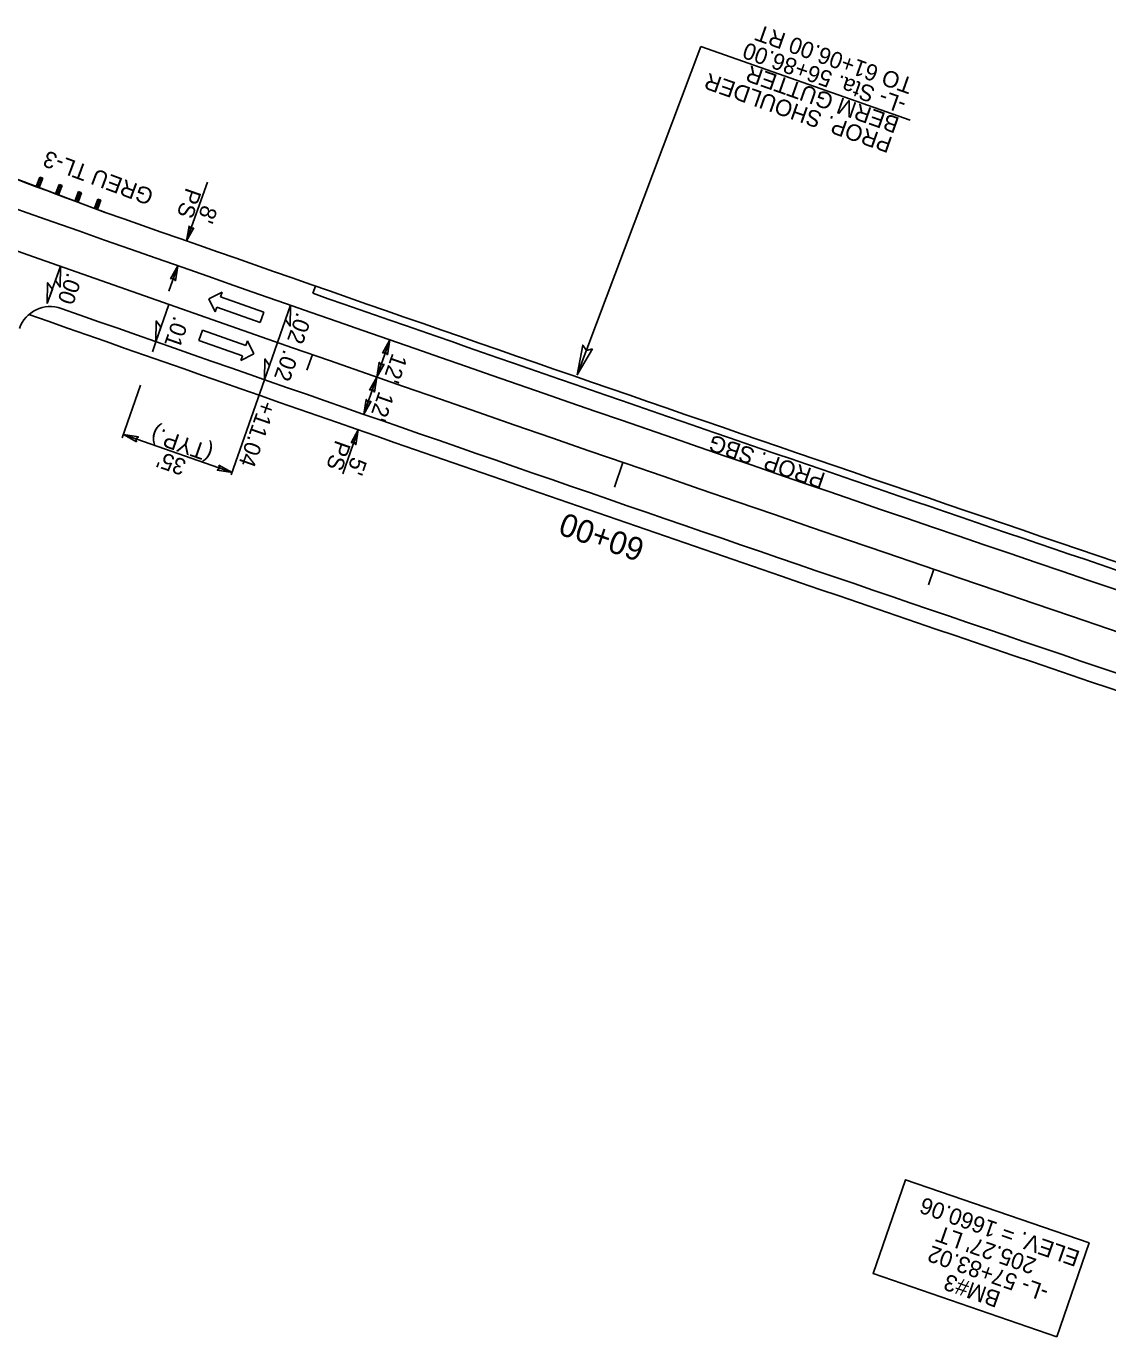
# Model space of a CAD drawing. Extents: x 472216 to 481979, y 489069 to 507339.
# Drawn here: x 479886.3 to 480215.3, y 493169 to 493567.7 of the extents above; entities that cross this region are included whole.
import ezdxf

# ---------------------------------------------------------------- set-up
doc = ezdxf.new("R2010")
doc.units = 0
for name, color, linetype in [('Exist Horizontal Alignment Point', 7, 'Continuous'), ('Prop Drainage Structure Drop Inlet Grate 2 Narrow Slots and Sag Grates 840 24 CELL', 7, 'Continuous'), ('Prop Drainage Structure Drop Inlet Grate 2 Wide Slots and Sag Grates 840 22 Label', 7, 'Continuous'), ('Prop Drainage Structure Outlet Berm Ditch 850 10 CELL', 7, 'Continuous'), ('Prop Drainage Structure Pipe CSP 15in', 7, 'Continuous'), ('Prop Drainage Structure Pipe Plug CELL', 7, 'Continuous'), ('Prop Drainage Structure Pipe RCP 24in Class III Label', 7, 'Continuous'), ('Prop Drainage Structure Pipe Side Drain 15in Label', 7, 'Continuous'), ('Prop Drainage Structure Tops and Inverts LABEL', 7, 'Continuous'), ('Prop Earthen Structure False Sump CELL', 7, 'Continuous'), ('Prop Erosion Embankment Toe Protection CELL', 7, 'Continuous'), ('Sheet Block Revision CELL', 7, 'Continuous'), ('Sheet North Arrow Point CELL', 7, 'Continuous'), ('Sheet PE Seal Cell', 7, 'Continuous'), ('Sheet Profile Grid Major CELL', 7, 'Continuous'), ('Sheet Profile Grid Minor CELL', 7, 'Continuous')]:
    doc.layers.add(name, color=color, linetype=linetype)

msp = doc.modelspace()

# ---------------------------------------------------------------- linework, layer by layer
at = {"layer": 'Exist Horizontal Alignment Point'}
msp.add_lwpolyline([(480199.77, 493168.96), (480143.94, 493188.2), (480153.78, 493216.75), (480209.61, 493197.51)], close=True, dxfattribs=at)
at = {"layer": 'Prop Drainage Structure Drop Inlet Grate 2 Narrow Slots and Sag Grates 840 24 CELL'}
for points in [[(479896.73, 493494.66), (479896.64, 493488.33), (479895.2, 493490.29)], [(479892.74, 493483.34), (479892.84, 493489.66), (479894.28, 493487.7)], [(479966.74, 493482.81), (479966.65, 493476.48), (479965.22, 493478.44)], [(479925.78, 493471.72), (479925.88, 493478.05), (479927.31, 493476.09)], [(479958.82, 493460.15), (479958.92, 493466.47), (479960.35, 493464.51)]]:
    msp.add_lwpolyline(points, close=True, dxfattribs=at)
at = {"layer": 'Prop Drainage Structure Drop Inlet Grate 2 Wide Slots and Sag Grates 840 22 Label'}
for p, q in [((479892.74, 493483.34), (479896.73, 493494.66)), ((479925.78, 493471.72), (479929.75, 493483.05)), ((479958.82, 493460.15), (479966.74, 493482.81)), ((479925.78, 493471.72), (479924.69, 493468.62)), ((479921.13, 493458.48), (479915.52, 493442.51)), ((479958.82, 493460.15), (479948.7, 493431.2)), ((479948.94, 493431.89), (479915.9, 493443.47))]:
    msp.add_line(p, q, dxfattribs=at)
for points in [[(479919.89, 493441.25), (479915.9, 493443.47), (479920.43, 493442.73), (479919.63, 493442.16)], [(479944.95, 493434.11), (479948.94, 493431.89), (479944.41, 493432.63), (479945.22, 493433.2)]]:
    msp.add_lwpolyline(points, close=True, dxfattribs=at)
at = {"layer": 'Prop Drainage Structure Outlet Berm Ditch 850 10 CELL'}
for points in [[(479937.34, 493506.35), (479935.12, 493502.36), (479935.86, 493506.89), (479936.43, 493506.09)], [(479930.24, 493490.82), (479932.46, 493494.81), (479931.72, 493490.28), (479931.15, 493491.09)], [(479994.74, 493468.27), (479996.96, 493472.26), (479996.21, 493467.73), (479995.65, 493468.53)], [(480058.54, 493469.54), (480053.92, 493461.66), (480055.61, 493470.69), (480056.7, 493469.05)], [(479995.2, 493464.93), (479992.98, 493460.94), (479993.73, 493465.47), (479994.29, 493464.66)], [(479990.76, 493456.95), (479992.98, 493460.94), (479992.24, 493456.4), (479991.67, 493457.21)], [(479991.23, 493453.61), (479989, 493449.62), (479989.75, 493454.15), (479990.31, 493453.34)], [(479985.12, 493440.91), (479987.34, 493444.9), (479986.6, 493440.37), (479986.03, 493441.17)]]:
    msp.add_lwpolyline(points, close=True, dxfattribs=at)
at = {"layer": 'Prop Drainage Structure Pipe Plug CELL'}
for p, q in [((479910.36, 493511.06), (479866.6, 493527.5)), ((479889.35, 493518.95), (479890.42, 493521.8)), ((479889.88, 493520.38), (479891.35, 493521.44)), ((479890.29, 493518.6), (479891.35, 493521.44)), ((479891.35, 493521.44), (479890.42, 493521.8)), ((479890.42, 493521.8), (479890.82, 493520.02)), ((479890.82, 493520.02), (479889.35, 493518.95)), ((479890.29, 493518.6), (479889.35, 493518.95)), ((479890.82, 493520.02), (479889.88, 493520.38)), ((479890.29, 493518.6), (479889.88, 493520.38)), ((479895.25, 493516.74), (479896.32, 493519.59)), ((479896.72, 493517.81), (479895.25, 493516.74)), ((479895.78, 493518.16), (479897.26, 493519.24)), ((479896.72, 493517.81), (479895.78, 493518.16)), ((479896.18, 493516.39), (479895.78, 493518.16)), ((479896.18, 493516.39), (479897.26, 493519.24)), ((479897.26, 493519.24), (479896.32, 493519.59)), ((479896.32, 493519.59), (479896.72, 493517.81)), ((479901.15, 493514.52), (479902.22, 493517.38)), ((479901.68, 493515.95), (479903.16, 493517.03)), ((479902.08, 493514.17), (479903.16, 493517.03)), ((479903.16, 493517.03), (479902.22, 493517.38)), ((479902.22, 493517.38), (479902.62, 493515.6)), ((479902.62, 493515.6), (479901.15, 493514.52)), ((479902.62, 493515.6), (479901.68, 493515.95)), ((479902.08, 493514.17), (479901.68, 493515.95)), ((479907.05, 493512.31), (479908.1, 493515.11)), ((479907.05, 493512.31), (479907.57, 493513.71)), ((479908.51, 493513.36), (479907.05, 493512.31)), ((479907.57, 493513.71), (479909.04, 493514.76)), ((479908.51, 493513.36), (479907.57, 493513.71)), ((479907.57, 493513.71), (479907.98, 493511.95)), ((479907.98, 493511.95), (479909.04, 493514.76)), ((479909.04, 493514.76), (479908.1, 493515.11)), ((479908.1, 493515.11), (479908.51, 493513.36)), ((479907.98, 493511.95), (479907.05, 493512.31))]:
    msp.add_line(p, q, dxfattribs=at)
at = {"layer": 'Prop Drainage Structure Pipe RCP 24in Class III Label'}
msp.add_line((479973.53, 493486.44), (479974.3, 493488.64), dxfattribs=at)
for centre, radius, start, end in [((489862.97, 521790.84), 29988, 250.329766, 251.348324), ((479893.66, 493472.41), 10, 70.6057, 160.5714), ((489862.97, 521790.84), 30012, 250.605735, 251.348326)]:
    msp.add_arc(centre, radius, start, end, dxfattribs=at)
at = {"layer": 'Prop Drainage Structure Pipe Side Drain 15in Label'}
for p, q in [((479941.88, 493484.77), (479945.91, 493486.74)), ((479943.82, 493480.8), (479941.88, 493484.77)), ((479945.91, 493486.74), (479945.41, 493485.32)), ((479945.41, 493485.32), (479958.62, 493480.67)), ((479944.32, 493482.21), (479943.82, 493480.8)), ((479957.52, 493477.56), (479944.32, 493482.21)), ((479958.62, 493480.67), (479957.52, 493477.56)), ((479938.87, 493472.09), (479939.96, 493475.2)), ((479939.96, 493475.2), (479953.17, 493470.55)), ((479952.07, 493467.44), (479938.87, 493472.09)), ((479953.17, 493470.55), (479953.67, 493471.97)), ((479953.67, 493471.97), (479955.61, 493468)), ((479955.61, 493468), (479951.57, 493466.02)), ((479951.57, 493466.02), (479952.07, 493467.44))]:
    msp.add_line(p, q, dxfattribs=at)
at = {"layer": 'Prop Drainage Structure Tops and Inverts LABEL'}
msp.add_arc((489862.97, 521790.84), 29980, 250.611313, 251.348132, dxfattribs=at)
at = {"layer": 'Prop Earthen Structure False Sump CELL'}
msp.add_arc((489862.97, 521790.84), 29982.33, 250.740797, 251.348204, dxfattribs=at)
at = {"layer": 'Prop Erosion Embankment Toe Protection CELL'}
for radius, start, end in [(29980, 250.611313, 251.348132), (30017, 250.589206, 251.348208)]:
    msp.add_arc((489862.97, 521790.84), radius, start, end, dxfattribs=at)
msp.add_spline([(479910.36, 493511.06), (479909.98, 493511.2), (479863.55, 493528.65)], degree=3, dxfattribs=at)
at = {"layer": 'Sheet Block Revision CELL'}
for p, q in [((480053.92, 493461.66), (480091.5, 493561.55)), ((480155.16, 493539.14), (480091.5, 493561.55)), ((479941.42, 493520.28), (479935.12, 493502.36)), ((479932.46, 493494.81), (479929.74, 493487.07)), ((479996.96, 493472.26), (479989, 493449.62)), ((479987.34, 493444.9), (479982.63, 493431.48))]:
    msp.add_line(p, q, dxfattribs=at)
at = {"layer": 'Sheet North Arrow Point CELL'}
msp.add_arc((489862.97, 521790.84), 30000, 250.329766, 251.788426, dxfattribs=at)
at = {"layer": 'Sheet PE Seal Cell'}
for p, q in [((479973.36, 493467.78), (479971.72, 493463.06)), ((480162.4, 493402.48), (480160.79, 493397.75))]:
    msp.add_line(p, q, dxfattribs=at)
at = {"layer": 'Sheet Profile Grid Minor CELL'}
msp.add_line((480067.83, 493434.97), (480065.22, 493427.41), dxfattribs=at)

# ---------------------------------------------------------------- texts
at = {"layer": 'Prop Drainage Structure Drop Inlet Grate 2 Narrow Slots and Sag Grates 840 24 CELL'}
for s, rotation, p in [('.00', 250.5972, (479898.86, 493492.99)), ('.01', 250.664, (479931.31, 493479.79)), ('.02', 250.7308, (479968.67, 493480.94)), ('.02', 250.664, (479964.71, 493469.61))]:
    msp.add_text(s, height=5, rotation=rotation, dxfattribs=at).set_placement(p)
at = {"layer": 'Prop Drainage Structure Drop Inlet Grate 2 Wide Slots and Sag Grates 840 22 Label'}
for s, rotation, p in [('+11.04', 250.6974, (479957.69, 493454.17)), ('(TYP.)', 160.6974, (479943.53, 493439.68)), ("35'", 160.6974, (479935.39, 493435.59))]:
    msp.add_text(s, height=5, rotation=rotation, dxfattribs=at).set_placement(p)
at = {"layer": 'Prop Drainage Structure Pipe CSP 15in'}
for s, rotation, p in [('TO 61+06.00 RT', 160.6046, (480156.48, 493551.68)), ('-L- Sta. 56+86.00', 160.6046, (480154.38, 493545.7)), ('PROP. SHOULDER ', 160.6046, (480150.17, 493533.74)), ('BERM GUTTER', 160.6046, (480152.27, 493539.72)), ('PS', 250.6323, (479935.01, 493518.81)), ("8'", 250.6323, (479939.89, 493513.59)), ("12'", 250.6323, (479997.71, 493468.47)), ("12'", 250.6323, (479993.64, 493456.89)), ('PS', 250.6323, (479980.45, 493442.04)), ('PROP. SBG', 160.9892, (480129.78, 493431.59)), ("5'", 250.6323, (479985.38, 493436.97)), ('ELEV. = 1660.06', 160.8192, (480207.2, 493194.88)), ("205.27' LT", 160.8192, (480193.95, 493192.55)), ('-L- 57+83.02', 160.8192, (480197.69, 493184.31)), ('BM#3', 160.8192, (480183.07, 493182.45))]:
    msp.add_text(s, height=5, rotation=rotation, dxfattribs=at).set_placement(p)
at = {"layer": 'Prop Drainage Structure Pipe Plug CELL'}
msp.add_text('GREU TL-3', height=5, rotation=159.558, dxfattribs=at).set_placement((479925.45, 493517.77))
at = {"layer": 'Sheet Profile Grid Major CELL'}
msp.add_text('60+00', height=7, rotation=160.9432, dxfattribs=at).set_placement((480074.94, 493411.29))

doc.saveas('drawing.dxf')
